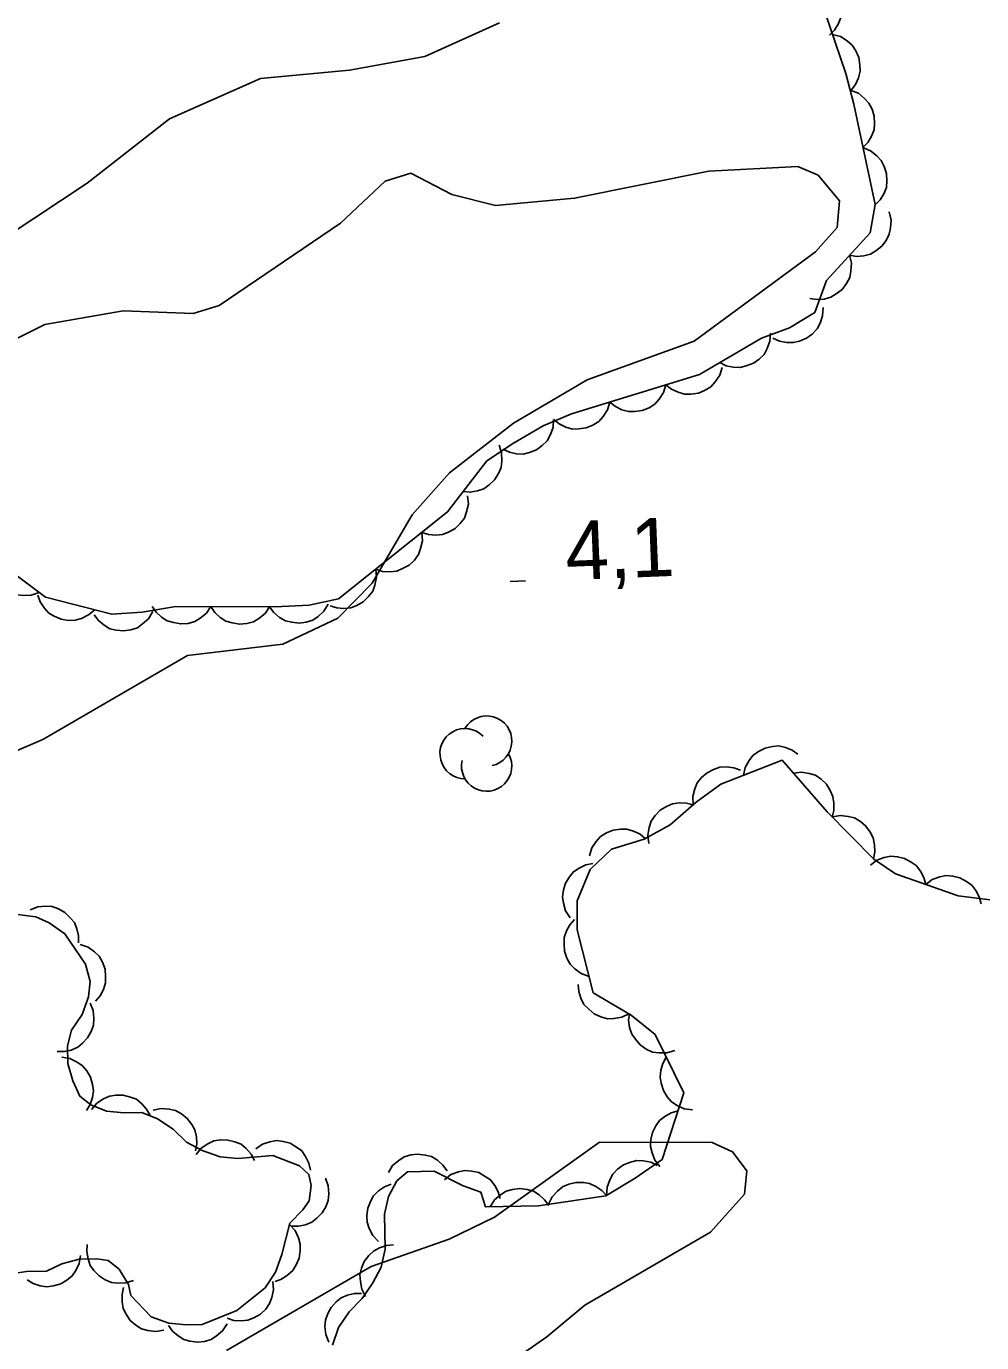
# Model space of a CAD drawing. Extents: x 336540 to 340074, y 5572036 to 5573747.
# Drawn here: x 337417.8 to 337466.6, y 5572748.1 to 5572815.4 of the extents above; entities that cross this region are included whole.
import ezdxf

# ---------------------------------------------------------------- set-up
doc = ezdxf.new("R2010")
doc.units = 0
for name, color, linetype in [('Niveau 1', 7, 'Continuous'), ('Niveau 3', 7, 'Continuous'), ('Niveau 44', 7, 'Continuous')]:
    doc.layers.add(name, color=color, linetype=linetype)

msp = doc.modelspace()

# ---------------------------------------------------------------- linework, layer by layer
at = {"layer": 'Niveau 1'}
for points in [[(337441.96, 5572815.56), (337438.15, 5572813.83), (337434.3, 5572813.13), (337429.75, 5572812.71), (337425.1, 5572810.64), (337420.89, 5572807.36), (337410.07, 5572800.19)], [(337415.24, 5572798.41), (337418.72, 5572800.12), (337422.73, 5572800.83), (337426.3, 5572800.68), (337427.64, 5572801.1), (337433.83, 5572805.31), (337436.12, 5572807.46), (337437.43, 5572807.86), (337439.52, 5572806.78), (337441.76, 5572806.22), (337445.8, 5572806.58), (337452.67, 5572807.97), (337457.22, 5572808.21), (337458.25, 5572807.76), (337459.35, 5572806.45), (337459.23, 5572805.09), (337458.11, 5572803.84), (337451.91, 5572799.28), (337446.44, 5572797.29), (337442.67, 5572795.08), (337439.41, 5572792.54), (337437.5, 5572790.4)], [(337437.5, 5572790.4), (337435.46, 5572786.9), (337433.7, 5572785.1), (337430.89, 5572783.77), (337426.01, 5572783.2), (337418.61, 5572778.9), (337414.16, 5572776.99), (337407.96, 5572775.32), (337404.93, 5572774.98), (337401.29, 5572773.77), (337387.21, 5572764.4), (337382.93, 5572762.15), (337371.82, 5572757.5), (337367.71, 5572755.26)], [(337428.01, 5572747.66), (337435.4, 5572751.95), (337439.39, 5572753.35), (337441.7, 5572754.47), (337447.08, 5572758.31), (337452.84, 5572758.29), (337453.88, 5572757.82), (337454.61, 5572756.84), (337454.49, 5572755.65), (337452.75, 5572753.7), (337446.32, 5572749.97), (337444.38, 5572748.35), (337437.68, 5572743.68)]]:
    msp.add_lwpolyline(points, dxfattribs=at)
at = {"layer": 'Niveau 3'}
msp.add_line((337442.5, 5572786.98), (337443.3, 5572787.02), dxfattribs=at)
at = {"layer": 'Niveau 44'}
for points in [[(337458.23, 5572817.86), (337458.62, 5572817.7), (337458.93, 5572817.44), (337459.16, 5572817.2), (337459.31, 5572816.88), (337459.42, 5572816.53), (337459.43, 5572816.15), (337459.41, 5572815.82), (337459.28, 5572815.49), (337459.09, 5572815.18), (337458.84, 5572814.92)], [(337458.58, 5572816.17), (337459.66, 5572812.96), (337460.07, 5572811.4), (337461.16, 5572806.27), (337460.91, 5572804.82), (337458.68, 5572802.38), (337458.09, 5572800.74), (337456.79, 5572799.95), (337455.35, 5572799.42), (337452.18, 5572797.57), (337445.65, 5572795.55), (337444.19, 5572794.95), (337442.67, 5572794.06), (337441.32, 5572793.15), (337439.31, 5572790.54), (337433.74, 5572786.09), (337432.24, 5572785.78), (337430.49, 5572785.69), (337425.42, 5572785.71), (337423.69, 5572785.41), (337422.15, 5572785.32), (337418.75, 5572786.18), (337416.08, 5572788.17)], [(337458.99, 5572814.96), (337459.39, 5572814.85), (337459.73, 5572814.63), (337459.99, 5572814.42), (337460.18, 5572814.12), (337460.33, 5572813.78), (337460.39, 5572813.41), (337460.4, 5572813.08), (337460.31, 5572812.74), (337460.16, 5572812.4), (337459.94, 5572812.11)], [(337459.92, 5572812.1), (337460.31, 5572811.95), (337460.62, 5572811.69), (337460.85, 5572811.45), (337461.01, 5572811.14), (337461.12, 5572810.78), (337461.13, 5572810.4), (337461.11, 5572810.08), (337460.98, 5572809.75), (337460.79, 5572809.43), (337460.54, 5572809.17)], [(337460.54, 5572809.17), (337460.93, 5572809.01), (337461.25, 5572808.76), (337461.47, 5572808.52), (337461.63, 5572808.2), (337461.74, 5572807.85), (337461.76, 5572807.47), (337461.74, 5572807.14), (337461.61, 5572806.81), (337461.42, 5572806.5), (337461.17, 5572806.24)], [(337461.88, 5572805.88), (337461.98, 5572805.47), (337461.95, 5572805.07), (337461.89, 5572804.74), (337461.73, 5572804.43), (337461.5, 5572804.14), (337461.2, 5572803.9), (337460.92, 5572803.73), (337460.58, 5572803.64), (337460.21, 5572803.61), (337459.86, 5572803.67)], [(337459.86, 5572803.67), (337459.95, 5572803.26), (337459.93, 5572802.85), (337459.87, 5572802.53), (337459.7, 5572802.22), (337459.48, 5572801.92), (337459.18, 5572801.69), (337458.9, 5572801.52), (337458.56, 5572801.43), (337458.19, 5572801.4), (337457.83, 5572801.45)], [(337458.5, 5572800.99), (337458.48, 5572800.57), (337458.35, 5572800.19), (337458.2, 5572799.9), (337457.95, 5572799.64), (337457.65, 5572799.43), (337457.3, 5572799.28), (337456.98, 5572799.2), (337456.63, 5572799.21), (337456.27, 5572799.28), (337455.94, 5572799.43)], [(337455.82, 5572799.69), (337455.79, 5572799.28), (337455.65, 5572798.9), (337455.49, 5572798.6), (337455.24, 5572798.36), (337454.94, 5572798.14), (337454.58, 5572798.01), (337454.26, 5572797.92), (337453.91, 5572797.94), (337453.55, 5572798.02), (337453.23, 5572798.18)], [(337453.34, 5572797.93), (337453.22, 5572797.53), (337452.99, 5572797.19), (337452.77, 5572796.94), (337452.47, 5572796.76), (337452.13, 5572796.62), (337451.75, 5572796.57), (337451.42, 5572796.56), (337451.09, 5572796.66), (337450.75, 5572796.82), (337450.47, 5572797.04)], [(337450.47, 5572797.04), (337450.35, 5572796.64), (337450.12, 5572796.3), (337449.9, 5572796.06), (337449.61, 5572795.87), (337449.26, 5572795.73), (337448.88, 5572795.68), (337448.56, 5572795.67), (337448.22, 5572795.77), (337447.89, 5572795.93), (337447.6, 5572796.15)], [(337447.6, 5572796.15), (337447.48, 5572795.76), (337447.26, 5572795.42), (337447.04, 5572795.17), (337446.74, 5572794.98), (337446.4, 5572794.84), (337446.02, 5572794.79), (337445.69, 5572794.78), (337445.35, 5572794.88), (337445.02, 5572795.04), (337444.74, 5572795.27)], [(337444.73, 5572795.27), (337444.7, 5572794.85), (337444.56, 5572794.47), (337444.4, 5572794.18), (337444.15, 5572793.93), (337443.85, 5572793.71), (337443.49, 5572793.58), (337443.18, 5572793.5), (337442.83, 5572793.51), (337442.47, 5572793.59), (337442.14, 5572793.75)], [(337441.94, 5572793.95), (337442.07, 5572793.56), (337442.08, 5572793.15), (337442.04, 5572792.82), (337441.91, 5572792.5), (337441.71, 5572792.19), (337441.43, 5572791.93), (337441.17, 5572791.73), (337440.83, 5572791.62), (337440.47, 5572791.55), (337440.11, 5572791.58)], [(337440.33, 5572791.36), (337440.37, 5572790.94), (337440.28, 5572790.54), (337440.17, 5572790.23), (337439.96, 5572789.95), (337439.69, 5572789.7), (337439.35, 5572789.51), (337439.05, 5572789.38), (337438.7, 5572789.35), (337438.33, 5572789.38), (337437.99, 5572789.48)], [(337437.99, 5572789.48), (337438.02, 5572789.07), (337437.93, 5572788.67), (337437.82, 5572788.36), (337437.61, 5572788.08), (337437.34, 5572787.82), (337437.01, 5572787.64), (337436.71, 5572787.51), (337436.36, 5572787.48), (337435.99, 5572787.5), (337435.64, 5572787.61)], [(337418.43, 5572786.42), (337418.03, 5572786.28), (337417.63, 5572786.27), (337417.3, 5572786.3), (337416.97, 5572786.43), (337416.66, 5572786.62), (337416.39, 5572786.9), (337416.19, 5572787.16), (337416.07, 5572787.49), (337416.01, 5572787.85), (337416.02, 5572788.21)], [(337435.64, 5572787.61), (337435.68, 5572787.2), (337435.59, 5572786.8), (337435.48, 5572786.49), (337435.27, 5572786.21), (337435, 5572785.95), (337434.67, 5572785.76), (337434.37, 5572785.64), (337434.01, 5572785.61), (337433.64, 5572785.63), (337433.3, 5572785.74)], [(337421.27, 5572785.54), (337420.96, 5572785.27), (337420.59, 5572785.09), (337420.27, 5572785), (337419.92, 5572784.99), (337419.56, 5572785.05), (337419.2, 5572785.21), (337418.92, 5572785.37), (337418.68, 5572785.63), (337418.48, 5572785.94), (337418.36, 5572786.28)], [(337424.24, 5572785.44), (337424.02, 5572785.08), (337423.72, 5572784.81), (337423.45, 5572784.62), (337423.12, 5572784.51), (337422.75, 5572784.46), (337422.37, 5572784.5), (337422.05, 5572784.57), (337421.75, 5572784.75), (337421.46, 5572784.98), (337421.24, 5572785.27)], [(337427.21, 5572785.7), (337426.98, 5572785.36), (337426.66, 5572785.1), (337426.38, 5572784.93), (337426.04, 5572784.84), (337425.67, 5572784.81), (337425.29, 5572784.88), (337424.98, 5572784.97), (337424.68, 5572785.16), (337424.41, 5572785.42), (337424.21, 5572785.71)], [(337430.21, 5572785.69), (337429.98, 5572785.35), (337429.66, 5572785.09), (337429.38, 5572784.92), (337429.04, 5572784.83), (337428.67, 5572784.8), (337428.29, 5572784.87), (337427.98, 5572784.96), (337427.68, 5572785.15), (337427.41, 5572785.4), (337427.21, 5572785.7)], [(337433.21, 5572785.83), (337432.99, 5572785.47), (337432.69, 5572785.2), (337432.42, 5572785.01), (337432.08, 5572784.91), (337431.72, 5572784.86), (337431.34, 5572784.9), (337431.02, 5572784.97), (337430.71, 5572785.15), (337430.43, 5572785.39), (337430.21, 5572785.68)], [(337454.43, 5572777.06), (337454.52, 5572777.47), (337454.72, 5572777.82), (337454.92, 5572778.09), (337455.21, 5572778.29), (337455.54, 5572778.46), (337455.91, 5572778.54), (337456.24, 5572778.57), (337456.58, 5572778.5), (337456.93, 5572778.36), (337457.22, 5572778.16)], [(337446.75, 5572765.94), (337445.94, 5572769.16), (337445.93, 5572770.65), (337446.6, 5572772.26), (337447.68, 5572773.3), (337449.35, 5572773.81), (337450.69, 5572774.54), (337452.02, 5572775.69), (337453.28, 5572776.61), (337456.41, 5572777.84), (337458.72, 5572775.2), (337461.09, 5572772.79), (337462.2, 5572772.03), (337465.41, 5572770.91), (337468.96, 5572770.46)], [(337451.86, 5572775.57), (337451.84, 5572775.99), (337451.94, 5572776.38), (337452.07, 5572776.69), (337452.29, 5572776.96), (337452.57, 5572777.2), (337452.91, 5572777.37), (337453.22, 5572777.49), (337453.57, 5572777.5), (337453.94, 5572777.46), (337454.28, 5572777.34)], [(337456.99, 5572777.18), (337457.4, 5572777.23), (337457.8, 5572777.17), (337458.12, 5572777.07), (337458.41, 5572776.87), (337458.67, 5572776.61), (337458.87, 5572776.29), (337459.01, 5572775.99), (337459.06, 5572775.64), (337459.05, 5572775.27), (337458.96, 5572774.93)], [(337449.6, 5572773.59), (337449.55, 5572774.01), (337449.62, 5572774.41), (337449.72, 5572774.72), (337449.92, 5572775.01), (337450.18, 5572775.28), (337450.5, 5572775.48), (337450.8, 5572775.62), (337451.15, 5572775.66), (337451.52, 5572775.65), (337451.87, 5572775.56)], [(337458.98, 5572774.94), (337459.39, 5572775.02), (337459.79, 5572774.97), (337460.11, 5572774.89), (337460.41, 5572774.71), (337460.69, 5572774.47), (337460.91, 5572774.16), (337461.07, 5572773.87), (337461.14, 5572773.52), (337461.15, 5572773.15), (337461.08, 5572772.8)], [(337446.56, 5572772.96), (337446.68, 5572773.36), (337446.91, 5572773.69), (337447.13, 5572773.94), (337447.43, 5572774.13), (337447.77, 5572774.26), (337448.15, 5572774.31), (337448.48, 5572774.32), (337448.81, 5572774.22), (337449.15, 5572774.06), (337449.43, 5572773.83)], [(337445.57, 5572769.79), (337445.34, 5572770.14), (337445.23, 5572770.53), (337445.18, 5572770.86), (337445.23, 5572771.21), (337445.34, 5572771.56), (337445.54, 5572771.88), (337445.74, 5572772.14), (337446.04, 5572772.33), (337446.37, 5572772.49), (337446.73, 5572772.56)], [(337460.92, 5572772.48), (337461.25, 5572772.73), (337461.63, 5572772.87), (337461.96, 5572772.93), (337462.31, 5572772.91), (337462.67, 5572772.82), (337463, 5572772.63), (337463.27, 5572772.45), (337463.48, 5572772.17), (337463.66, 5572771.84), (337463.75, 5572771.49)], [(337463.75, 5572771.49), (337464.08, 5572771.74), (337464.47, 5572771.88), (337464.79, 5572771.95), (337465.14, 5572771.92), (337465.5, 5572771.83), (337465.83, 5572771.64), (337466.1, 5572771.46), (337466.31, 5572771.18), (337466.49, 5572770.85), (337466.58, 5572770.5)], [(337416.68, 5572770.03), (337418.26, 5572769.84), (337418.95, 5572769.52), (337419.75, 5572768.97), (337420.8, 5572767.42), (337421.04, 5572766.53), (337420.95, 5572765.74), (337420.63, 5572764.83), (337420.09, 5572764.03), (337419.88, 5572763.23), (337419.9, 5572762.33), (337420.15, 5572761.44), (337420.51, 5572760.66), (337421.08, 5572760.22), (337421.88, 5572759.9), (337422.78, 5572759.81), (337423.68, 5572759.83), (337424.48, 5572759.51), (337425.28, 5572758.97), (337425.97, 5572758.31), (337426.77, 5572757.88), (337427.68, 5572757.56), (337428.58, 5572757.47), (337430.38, 5572757.63), (337431.74, 5572757.1), (337432.21, 5572756.66), (337432.33, 5572756.1), (337432.24, 5572755.31), (337431.91, 5572754.85), (337431.25, 5572754.16), (337430.84, 5572752.57), (337430.52, 5572751.66), (337429.98, 5572750.86), (337428.54, 5572749.7), (337426.76, 5572748.98), (337425.97, 5572748.96), (337425.06, 5572749.05), (337424.16, 5572749.37), (337423.12, 5572750.47), (337422.99, 5572751.03), (337422.52, 5572751.81), (337421.95, 5572752.25), (337421.38, 5572752.34), (337420.48, 5572752.32), (337419.59, 5572752.08), (337418.81, 5572751.72), (337417.79, 5572751.7), (337416, 5572751.43)], [(337417.97, 5572770.19), (337418.36, 5572770.35), (337418.76, 5572770.38), (337419.09, 5572770.36), (337419.42, 5572770.24), (337419.75, 5572770.06), (337420.02, 5572769.79), (337420.23, 5572769.54), (337420.36, 5572769.22), (337420.44, 5572768.86), (337420.44, 5572768.5)], [(337446.54, 5572766.79), (337446.14, 5572766.94), (337445.82, 5572767.18), (337445.58, 5572767.41), (337445.41, 5572767.72), (337445.29, 5572768.07), (337445.26, 5572768.45), (337445.27, 5572768.78), (337445.39, 5572769.11), (337445.56, 5572769.43), (337445.8, 5572769.7)], [(337420.53, 5572768.42), (337420.93, 5572768.28), (337421.26, 5572768.04), (337421.49, 5572767.82), (337421.67, 5572767.51), (337421.8, 5572767.16), (337421.83, 5572766.78), (337421.83, 5572766.46), (337421.72, 5572766.12), (337421.55, 5572765.79), (337421.31, 5572765.52)], [(337433.42, 5572747.92), (337433.74, 5572748.83), (337434.28, 5572749.63), (337434.94, 5572750.32), (337435.49, 5572751.12), (337435.92, 5572751.92), (337436.12, 5572752.83), (337436.08, 5572754.63), (337436.28, 5572755.53), (337436.71, 5572756.33), (337437.26, 5572756.79), (337438.62, 5572756.83), (337440.1, 5572756.07), (337441.01, 5572755.76), (337441.24, 5572755), (337443.96, 5572755.06), (337447.4, 5572755.57), (337448.9, 5572756.46), (337450.28, 5572757.43), (337451.39, 5572760.84), (337449.92, 5572763.81), (337448.7, 5572764.81), (337446.75, 5572765.94)], [(337448.58, 5572764.88), (337448.21, 5572764.7), (337447.81, 5572764.63), (337447.48, 5572764.62), (337447.14, 5572764.72), (337446.8, 5572764.87), (337446.51, 5572765.12), (337446.28, 5572765.35), (337446.12, 5572765.67), (337446.01, 5572766.02), (337445.99, 5572766.38)], [(337421.03, 5572765.42), (337421.19, 5572765.04), (337421.22, 5572764.63), (337421.21, 5572764.3), (337421.09, 5572763.97), (337420.91, 5572763.65), (337420.65, 5572763.37), (337420.4, 5572763.16), (337420.07, 5572763.02), (337419.71, 5572762.94), (337419.35, 5572762.94)], [(337450.92, 5572762.99), (337450.52, 5572762.87), (337450.11, 5572762.88), (337449.78, 5572762.92), (337449.46, 5572763.07), (337449.16, 5572763.28), (337448.91, 5572763.57), (337448.72, 5572763.83), (337448.61, 5572764.17), (337448.56, 5572764.54), (337448.6, 5572764.89)], [(337419.59, 5572762.65), (337420, 5572762.58), (337420.37, 5572762.4), (337420.64, 5572762.22), (337420.87, 5572761.95), (337421.05, 5572761.63), (337421.15, 5572761.26), (337421.2, 5572760.94), (337421.15, 5572760.59), (337421.03, 5572760.23), (337420.85, 5572759.93)], [(337451.82, 5572759.97), (337451.41, 5572760.02), (337451.04, 5572760.19), (337450.76, 5572760.37), (337450.53, 5572760.63), (337450.34, 5572760.95), (337450.23, 5572761.32), (337450.17, 5572761.64), (337450.21, 5572761.99), (337450.31, 5572762.34), (337450.49, 5572762.66)], [(337421.11, 5572759.98), (337421.38, 5572760.3), (337421.72, 5572760.52), (337422.02, 5572760.66), (337422.36, 5572760.72), (337422.73, 5572760.72), (337423.1, 5572760.61), (337423.41, 5572760.5), (337423.68, 5572760.27), (337423.92, 5572760), (337424.1, 5572759.68)], [(337424.26, 5572759.94), (337424.67, 5572760.03), (337425.08, 5572760), (337425.4, 5572759.93), (337425.71, 5572759.76), (337426, 5572759.52), (337426.23, 5572759.22), (337426.39, 5572758.94), (337426.47, 5572758.59), (337426.49, 5572758.22), (337426.43, 5572757.87)], [(337450.16, 5572757.06), (337449.9, 5572757.39), (337449.76, 5572757.77), (337449.68, 5572758.09), (337449.7, 5572758.44), (337449.78, 5572758.8), (337449.96, 5572759.14), (337450.14, 5572759.41), (337450.42, 5572759.63), (337450.74, 5572759.81), (337451.09, 5572759.91)], [(337426.45, 5572757.68), (337426.72, 5572758), (337427.06, 5572758.23), (337427.36, 5572758.37), (337427.71, 5572758.43), (337428.08, 5572758.42), (337428.44, 5572758.32), (337428.75, 5572758.2), (337429.02, 5572757.98), (337429.27, 5572757.7), (337429.44, 5572757.38)], [(337429.5, 5572757.97), (337429.84, 5572758.21), (337430.23, 5572758.33), (337430.56, 5572758.39), (337430.91, 5572758.35), (337431.26, 5572758.25), (337431.59, 5572758.05), (337431.85, 5572757.86), (337432.05, 5572757.57), (337432.22, 5572757.23), (337432.3, 5572756.88)], [(337436.28, 5572756.76), (337436.5, 5572757.11), (337436.81, 5572757.38), (337437.09, 5572757.56), (337437.43, 5572757.66), (337437.79, 5572757.7), (337438.17, 5572757.65), (337438.49, 5572757.57), (337438.79, 5572757.39), (337439.07, 5572757.14), (337439.28, 5572756.85)], [(337447.44, 5572755.59), (337447.46, 5572756.01), (337447.6, 5572756.39), (337447.76, 5572756.68), (337448, 5572756.93), (337448.3, 5572757.15), (337448.66, 5572757.29), (337448.98, 5572757.37), (337449.33, 5572757.35), (337449.69, 5572757.28), (337450.02, 5572757.12)], [(337433.07, 5572756.46), (337433.21, 5572756.07), (337433.23, 5572755.66), (337433.21, 5572755.33), (337433.08, 5572755), (337432.9, 5572754.69), (337432.62, 5572754.42), (337432.37, 5572754.21), (337432.04, 5572754.09), (337431.68, 5572754.01), (337431.32, 5572754.02)], [(337439.15, 5572756.39), (337439.48, 5572756.65), (337439.86, 5572756.79), (337440.19, 5572756.86), (337440.54, 5572756.83), (337440.9, 5572756.75), (337441.23, 5572756.56), (337441.5, 5572756.38), (337441.72, 5572756.1), (337441.89, 5572755.77), (337441.99, 5572755.43)], [(337435.77, 5572753.23), (337435.48, 5572753.54), (337435.3, 5572753.9), (337435.19, 5572754.21), (337435.18, 5572754.56), (337435.23, 5572754.93), (337435.37, 5572755.28), (337435.53, 5572755.57), (337435.78, 5572755.82), (337436.09, 5572756.03), (337436.42, 5572756.16)], [(337441.48, 5572755.01), (337441.71, 5572755.36), (337442.02, 5572755.62), (337442.3, 5572755.8), (337442.63, 5572755.89), (337443, 5572755.94), (337443.38, 5572755.88), (337443.7, 5572755.8), (337443.99, 5572755.61), (337444.27, 5572755.36), (337444.48, 5572755.07)], [(337444.47, 5572755.14), (337444.66, 5572755.51), (337444.93, 5572755.81), (337445.18, 5572756.02), (337445.51, 5572756.16), (337445.87, 5572756.25), (337446.25, 5572756.24), (337446.57, 5572756.2), (337446.89, 5572756.05), (337447.2, 5572755.84), (337447.44, 5572755.58)], [(337431.23, 5572754.1), (337431.51, 5572753.79), (337431.68, 5572753.42), (337431.78, 5572753.1), (337431.78, 5572752.75), (337431.72, 5572752.38), (337431.56, 5572752.03), (337431.4, 5572751.75), (337431.14, 5572751.52), (337430.82, 5572751.31), (337430.49, 5572751.19)], [(337423.26, 5572751.24), (337422.86, 5572751.11), (337422.46, 5572751.1), (337422.13, 5572751.13), (337421.81, 5572751.27), (337421.49, 5572751.47), (337421.23, 5572751.75), (337421.04, 5572752.01), (337420.93, 5572752.35), (337420.86, 5572752.71), (337420.89, 5572753.07)], [(337435.12, 5572750.42), (337434.92, 5572750.79), (337434.85, 5572751.19), (337434.83, 5572751.52), (337434.91, 5572751.86), (337435.05, 5572752.2), (337435.29, 5572752.51), (337435.52, 5572752.74), (337435.83, 5572752.91), (337436.18, 5572753.03), (337436.54, 5572753.06)], [(337420.55, 5572752.52), (337420.48, 5572752.11), (337420.3, 5572751.75), (337420.12, 5572751.47), (337419.85, 5572751.25), (337419.53, 5572751.06), (337419.16, 5572750.96), (337418.83, 5572750.91), (337418.49, 5572750.96), (337418.13, 5572751.08), (337417.82, 5572751.27)], [(337430.38, 5572751.18), (337430.41, 5572750.76), (337430.33, 5572750.36), (337430.21, 5572750.05), (337430.01, 5572749.77), (337429.74, 5572749.51), (337429.4, 5572749.33), (337429.1, 5572749.2), (337428.75, 5572749.17), (337428.38, 5572749.19), (337428.04, 5572749.3)], [(337424.8, 5572748.69), (337424.39, 5572748.62), (337423.99, 5572748.68), (337423.67, 5572748.76), (337423.37, 5572748.95), (337423.09, 5572749.19), (337422.88, 5572749.51), (337422.73, 5572749.8), (337422.67, 5572750.15), (337422.67, 5572750.52), (337422.74, 5572750.87)], [(337433.24, 5572748.08), (337433.08, 5572748.47), (337433.04, 5572748.88), (337433.06, 5572749.21), (337433.18, 5572749.54), (337433.35, 5572749.86), (337433.62, 5572750.14), (337433.87, 5572750.35), (337434.19, 5572750.48), (337434.55, 5572750.57), (337434.91, 5572750.57)], [(337428.04, 5572749.01), (337427.81, 5572748.66), (337427.5, 5572748.4), (337427.22, 5572748.22), (337426.89, 5572748.12), (337426.52, 5572748.08), (337426.14, 5572748.13), (337425.82, 5572748.21), (337425.53, 5572748.4), (337425.25, 5572748.64), (337425.04, 5572748.94)]]:
    msp.add_lwpolyline(points, dxfattribs=at)
for centre, start, end in [((337441.307, 5572778.822), 282.26917, 149.72626), ((337440.202, 5572778.179), 44.11537, 269.80396), ((337441.307, 5572777.537), 166.93686, 29.62123)]:
    msp.add_arc(centre, 1.285, start, end, dxfattribs=at)

# ---------------------------------------------------------------- texts
at = {"layer": 'Niveau 3'}
msp.add_text('4,1    ', height=2.9999, rotation=2.27627, dxfattribs=at).set_placement((337445.38, 5572787.05))

doc.saveas('drawing.dxf')
